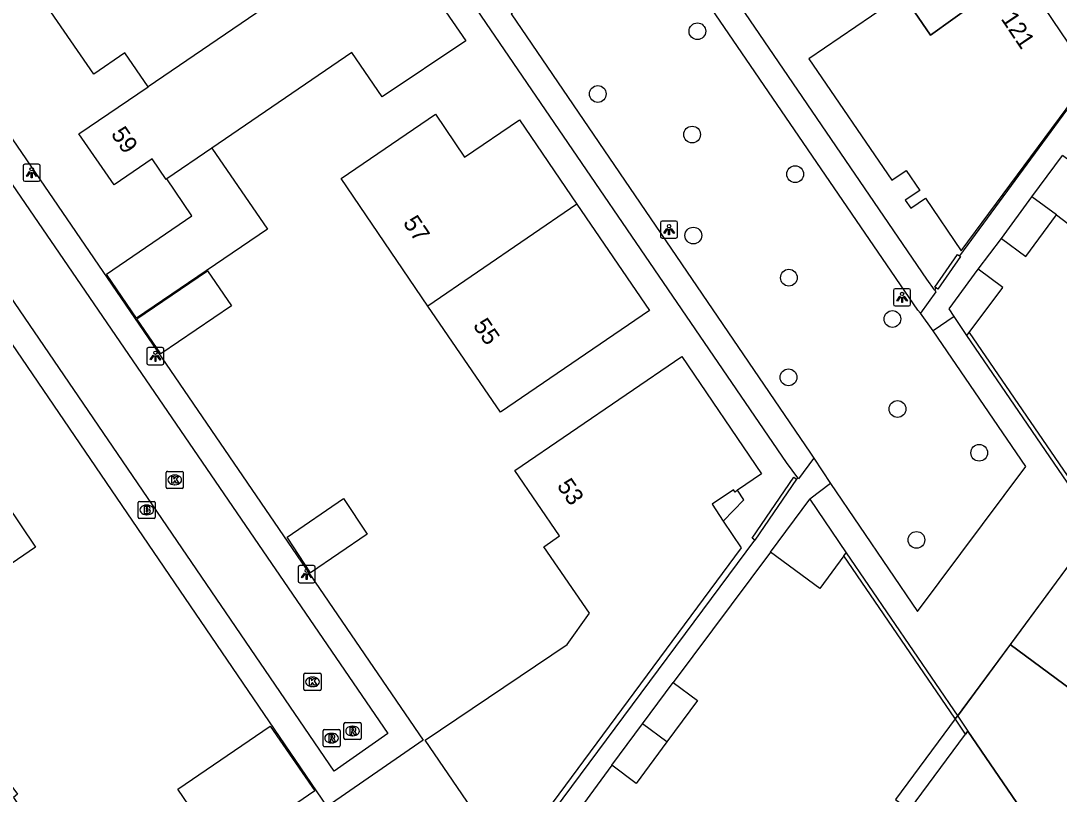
# Model space of a CAD drawing. Extents: x 155275 to 156263, y 382654 to 383635.
# Drawn here: x 155711 to 155771.6, y 383268.4 to 383313.6 of the extents above; entities that cross this region are included whole.
import ezdxf

# ---------------------------------------------------------------- set-up
doc = ezdxf.new("R2010")
doc.units = 0
for name, color, linetype in [('IMGEO_Boom', 7, 'Continuous'), ('IMGEO_Brandkraan', 7, 'Continuous'), ('IMGEO_Kolk', 7, 'Continuous'), ('IMGEO_Lichtpunt', 7, 'Continuous'), ('IMGEO_Muur', 7, 'Continuous'), ('IMGEO_Pand', 7, 'Continuous'), ('IMGEO_Pand_nummerreeks', 7, 'Continuous'), ('IMGEO_Pand_overbouw', 7, 'Continuous'), ('IMGEO_Rijbaan_lokaal_open', 7, 'Continuous'), ('IMGEO_Rioolput', 7, 'Continuous'), ('IMGEO_Voetpad_open', 7, 'Continuous')]:
    doc.layers.add(name, color=color, linetype=linetype)

msp = doc.modelspace()

# ---------------------------------------------------------------- linework, layer by layer
at = {"layer": 'IMGEO_Boom'}
for centre in [(155750.478, 383312.989), (155744.662, 383309.328), (155750.169, 383306.957), (155756.185, 383304.644), (155750.242, 383301.061), (155755.82, 383298.6), (155761.863, 383296.189), (155755.8, 383292.782), (155762.162, 383290.934), (155766.932, 383288.378), (155763.268, 383283.288)]:
    msp.add_circle(centre, 0.489, dxfattribs=at)
at = {"layer": 'IMGEO_Brandkraan'}
for p, q in [((155717.827, 383284.614), (155717.827, 383285.466)), ((155717.902, 383285.54), (155718.754, 383285.54)), ((155718.828, 383285.466), (155718.828, 383284.614)), ((155718.338, 383284.76), (155718.313, 383284.76)), ((155718.315, 383285.32), (155718.34, 383285.32)), ((155718.754, 383284.54), (155717.902, 383284.54))]:
    msp.add_line(p, q, dxfattribs=at)
for points in [[(155717.827, 383284.614), (155717.827, 383285.466)], [(155717.902, 383285.54), (155718.754, 383285.54)], [(155718.828, 383285.466), (155718.828, 383284.614)], [(155718.175, 383285.24), (155718.175, 383284.84), (155718.388, 383284.84)], [(155718.406, 383285.24), (155718.175, 383285.24)], [(155718.354, 383285.159), (155718.3, 383285.159), (155718.3, 383285.083)], [(155718.3, 383285.083), (155718.353, 383285.083)], [(155718.362, 383285.007), (155718.3, 383285.007), (155718.3, 383284.926)], [(155718.3, 383284.926), (155718.362, 383284.926)], [(155718.754, 383284.54), (155717.902, 383284.54)]]:
    msp.add_lwpolyline(points, dxfattribs=at)
for centre, radius, start, end in [((155717.904, 383285.464), 0.0765, 91.55205, 178.44795), ((155717.904, 383285.464), 0.0765, 91.55205, 178.44795), ((155718.752, 383285.464), 0.0765, 1.55205, 88.44795), ((155718.752, 383285.464), 0.0765, 1.55205, 88.44795), ((155718.355, 383285.121), 0.0379, 267.82845, 90.93552), ((155718.363, 383284.966), 0.0404, 269.87594, 90.50774), ((155718.394, 383285.091), 0.251, 268.66757, 293.53466), ((155718.41, 383285.095), 0.145, 59.4692, 91.53667), ((155718.435, 383285.142), 0.0922, 285.51372, 58.15012), ((155718.44, 383284.95), 0.105, 301.31148, 78.98903), ((155717.904, 383284.616), 0.0765, 181.55205, 268.44795), ((155717.904, 383284.616), 0.0765, 181.55205, 268.44795), ((155718.752, 383284.616), 0.0765, 271.55205, 358.44795), ((155718.752, 383284.616), 0.0765, 271.55205, 358.44795)]:
    msp.add_arc(centre, radius, start, end, dxfattribs=at)
for centre, major_axis, ratio, start_param, end_param in [((155718.314, 383285.04), (-0.387, 0.002), 0.722429, 4.712389, 7.853982), ((155718.339, 383285.04), (-0.39, 0.002), 0.717154, 1.570796, 4.712389)]:
    msp.add_ellipse(centre, major_axis=major_axis, ratio=ratio, start_param=start_param, end_param=end_param, dxfattribs=at)
at = {"layer": 'IMGEO_Kolk'}
for p, q in [((155719.465, 383286.367), (155719.465, 383287.219)), ((155719.54, 383287.293), (155720.392, 383287.293)), ((155720.466, 383287.219), (155720.466, 383286.367)), ((155719.953, 383287.073), (155719.978, 383287.073)), ((155720.392, 383286.293), (155719.54, 383286.293)), ((155719.976, 383286.513), (155719.951, 383286.513)), ((155727.507, 383274.576), (155727.507, 383275.428)), ((155727.582, 383275.502), (155728.434, 383275.502)), ((155727.995, 383275.282), (155728.02, 383275.282)), ((155728.508, 383275.428), (155728.508, 383274.576)), ((155728.434, 383274.502), (155727.582, 383274.502)), ((155728.018, 383274.722), (155727.993, 383274.722))]:
    msp.add_line(p, q, dxfattribs=at)
for points in [[(155719.465, 383286.367), (155719.465, 383287.219)], [(155719.54, 383287.293), (155720.392, 383287.293)], [(155720.466, 383287.219), (155720.466, 383286.367)], [(155719.786, 383286.993), (155719.909, 383286.993), (155719.909, 383286.842), (155720.039, 383286.993), (155720.203, 383286.993), (155720.057, 383286.842), (155720.21, 383286.593), (155720.058, 383286.593), (155719.973, 383286.757), (155719.909, 383286.69), (155719.909, 383286.593), (155719.786, 383286.593), (155719.786, 383286.993)], [(155720.392, 383286.293), (155719.54, 383286.293)], [(155727.507, 383274.576), (155727.507, 383275.428)], [(155727.582, 383275.502), (155728.434, 383275.502)], [(155727.828, 383275.202), (155727.951, 383275.202), (155727.951, 383275.051), (155728.081, 383275.202), (155728.245, 383275.202), (155728.099, 383275.051), (155728.252, 383274.802), (155728.1, 383274.802), (155728.015, 383274.966), (155727.951, 383274.899), (155727.951, 383274.802), (155727.828, 383274.802), (155727.828, 383275.202)], [(155728.508, 383275.428), (155728.508, 383274.576)], [(155728.434, 383274.502), (155727.582, 383274.502)]]:
    msp.add_lwpolyline(points, dxfattribs=at)
for centre, start, end in [((155719.542, 383287.217), 91.55205, 178.44795), ((155719.542, 383287.217), 91.55205, 178.44795), ((155720.39, 383287.217), 1.55205, 88.44795), ((155720.39, 383287.217), 1.55205, 88.44795), ((155719.542, 383286.369), 181.55205, 268.44795), ((155719.542, 383286.369), 181.55205, 268.44795), ((155720.39, 383286.369), 271.55205, 358.44795), ((155720.39, 383286.369), 271.55205, 358.44795), ((155727.584, 383275.426), 91.55205, 178.44795), ((155727.584, 383275.426), 91.55205, 178.44795), ((155728.432, 383275.426), 1.55205, 88.44795), ((155728.432, 383275.426), 1.55205, 88.44795), ((155727.584, 383274.578), 181.55205, 268.44795), ((155727.584, 383274.578), 181.55205, 268.44795), ((155728.432, 383274.578), 271.55205, 358.44795), ((155728.432, 383274.578), 271.55205, 358.44795)]:
    msp.add_arc(centre, 0.0765, start, end, dxfattribs=at)
for centre, major_axis, ratio, start_param, end_param in [((155719.952, 383286.793), (-0.387, 0.002), 0.722429, 4.712389, 7.853982), ((155719.977, 383286.793), (-0.39, 0.002), 0.717154, 1.570796, 4.712389), ((155727.994, 383275.002), (-0.387, 0.002), 0.722429, 4.712389, 7.853982), ((155728.019, 383275.002), (-0.39, 0.002), 0.717154, 1.570796, 4.712389)]:
    msp.add_ellipse(centre, major_axis=major_axis, ratio=ratio, start_param=start_param, end_param=end_param, dxfattribs=at)
at = {"layer": 'IMGEO_Lichtpunt'}
for p, q in [((155711.114, 383305.133), (155711.114, 383304.326)), ((155711.114, 383305.133), (155711.114, 383304.326)), ((155712.016, 383305.228), (155711.208, 383305.228)), ((155712.016, 383305.228), (155711.208, 383305.228)), ((155712.11, 383304.326), (155712.11, 383305.133)), ((155712.11, 383304.326), (155712.11, 383305.133)), ((155711.208, 383304.232), (155712.016, 383304.232)), ((155711.208, 383304.232), (155712.016, 383304.232)), ((155748.325, 383301.812), (155748.325, 383301.005)), ((155748.325, 383301.812), (155748.325, 383301.005)), ((155749.227, 383301.907), (155748.419, 383301.907)), ((155749.227, 383301.907), (155748.419, 383301.907)), ((155749.321, 383301.005), (155749.321, 383301.812)), ((155749.321, 383301.005), (155749.321, 383301.812)), ((155748.419, 383300.911), (155749.227, 383300.911)), ((155748.419, 383300.911), (155749.227, 383300.911)), ((155761.93, 383297.854), (155761.93, 383297.047)), ((155761.93, 383297.854), (155761.93, 383297.047)), ((155762.832, 383297.949), (155762.024, 383297.949)), ((155762.832, 383297.949), (155762.024, 383297.949)), ((155762.926, 383297.047), (155762.926, 383297.854)), ((155762.926, 383297.047), (155762.926, 383297.854)), ((155762.024, 383296.953), (155762.832, 383296.953)), ((155762.024, 383296.953), (155762.832, 383296.953)), ((155719.238, 383294.516), (155718.43, 383294.516)), ((155719.238, 383294.516), (155718.43, 383294.516)), ((155718.336, 383294.421), (155718.336, 383293.614)), ((155718.336, 383294.421), (155718.336, 383293.614)), ((155719.332, 383293.614), (155719.332, 383294.421)), ((155719.332, 383293.614), (155719.332, 383294.421)), ((155718.43, 383293.52), (155719.238, 383293.52)), ((155718.43, 383293.52), (155719.238, 383293.52)), ((155728.072, 383281.788), (155727.264, 383281.788)), ((155728.072, 383281.788), (155727.264, 383281.788)), ((155727.17, 383281.693), (155727.17, 383280.886)), ((155727.17, 383281.693), (155727.17, 383280.886)), ((155728.166, 383280.886), (155728.166, 383281.693)), ((155728.166, 383280.886), (155728.166, 383281.693)), ((155727.264, 383280.792), (155728.072, 383280.792)), ((155727.264, 383280.792), (155728.072, 383280.792))]:
    msp.add_line(p, q, dxfattribs=at)
for points in [[(155711.488, 383304.797), (155711.527, 383304.769), (155711.339, 383304.507), (155711.301, 383304.534), (155711.488, 383304.797)], [(155711.7, 383304.769), (155711.738, 383304.796), (155711.925, 383304.534), (155711.886, 383304.506), (155711.7, 383304.769)], [(155711.59, 383304.749), (155711.637, 383304.749), (155711.637, 383304.427), (155711.59, 383304.427), (155711.59, 383304.749)], [(155748.699, 383301.476), (155748.738, 383301.448), (155748.55, 383301.186), (155748.512, 383301.213), (155748.699, 383301.476)], [(155748.801, 383301.428), (155748.848, 383301.428), (155748.848, 383301.106), (155748.801, 383301.106), (155748.801, 383301.428)], [(155748.911, 383301.448), (155748.949, 383301.475), (155749.136, 383301.213), (155749.097, 383301.185), (155748.911, 383301.448)], [(155762.304, 383297.518), (155762.343, 383297.49), (155762.155, 383297.228), (155762.117, 383297.255), (155762.304, 383297.518)], [(155762.516, 383297.49), (155762.554, 383297.517), (155762.741, 383297.255), (155762.702, 383297.227), (155762.516, 383297.49)], [(155762.406, 383297.47), (155762.453, 383297.47), (155762.453, 383297.148), (155762.406, 383297.148), (155762.406, 383297.47)], [(155718.71, 383294.085), (155718.749, 383294.057), (155718.561, 383293.795), (155718.523, 383293.822), (155718.71, 383294.085)], [(155718.812, 383294.037), (155718.859, 383294.037), (155718.859, 383293.715), (155718.812, 383293.715), (155718.812, 383294.037)], [(155718.922, 383294.057), (155718.96, 383294.084), (155719.147, 383293.822), (155719.108, 383293.794), (155718.922, 383294.057)], [(155727.544, 383281.357), (155727.583, 383281.329), (155727.395, 383281.067), (155727.357, 383281.094), (155727.544, 383281.357)], [(155727.646, 383281.309), (155727.693, 383281.309), (155727.693, 383280.987), (155727.646, 383280.987), (155727.646, 383281.309)], [(155727.756, 383281.329), (155727.794, 383281.356), (155727.981, 383281.094), (155727.942, 383281.066), (155727.756, 383281.329)]]:
    msp.add_lwpolyline(points, dxfattribs=at)
for centre in [(155711.613, 383304.931), (155748.824, 383301.61), (155762.429, 383297.652), (155718.835, 383294.219), (155727.669, 383281.491)]:
    msp.add_circle(centre, 0.0994, dxfattribs=at)
for centre, start, end in [((155711.208, 383305.133), 90, 180), ((155711.208, 383305.133), 90, 180), ((155712.016, 383305.133), 0, 90), ((155712.016, 383305.133), 0, 90), ((155711.208, 383304.326), 180, 270), ((155711.208, 383304.326), 180, 270), ((155712.016, 383304.326), 270, 0), ((155712.016, 383304.326), 270, 360), ((155748.419, 383301.812), 90, 180), ((155748.419, 383301.812), 90, 180), ((155749.227, 383301.812), 0, 90), ((155749.227, 383301.812), 0, 90), ((155748.419, 383301.005), 180, 270), ((155748.419, 383301.005), 180, 270), ((155749.227, 383301.005), 270, 0), ((155749.227, 383301.005), 270, 360), ((155762.024, 383297.854), 90, 180), ((155762.024, 383297.854), 90, 180), ((155762.832, 383297.854), 0, 90), ((155762.832, 383297.854), 0, 90), ((155762.024, 383297.047), 180, 270), ((155762.024, 383297.047), 180, 270), ((155762.832, 383297.047), 270, 0), ((155762.832, 383297.047), 270, 360), ((155718.43, 383294.421), 90, 180), ((155718.43, 383294.421), 90, 180), ((155719.238, 383294.421), 0, 90), ((155719.238, 383294.421), 0, 90), ((155718.43, 383293.614), 180, 270), ((155718.43, 383293.614), 180, 270), ((155719.238, 383293.614), 270, 0), ((155719.238, 383293.614), 270, 360), ((155727.264, 383281.693), 90, 180), ((155727.264, 383281.693), 90, 180), ((155728.072, 383281.693), 0, 90), ((155728.072, 383281.693), 0, 90), ((155727.264, 383280.886), 180, 270), ((155727.264, 383280.886), 180, 270), ((155728.072, 383280.886), 270, 0), ((155728.072, 383280.886), 270, 360)]:
    msp.add_arc(centre, 0.0946, start, end, dxfattribs=at)
at = {"layer": 'IMGEO_Muur'}
for points in [[(155764.413, 383298.003), (155764.346, 383298.049), (155765.665, 383299.955), (155765.785, 383299.873)], [(155765.785, 383299.873), (155765.83, 383299.841), (155764.511, 383297.935), (155764.413, 383298.003)], [(155773.847, 383284.078), (155766.213, 383295.227)], [(155766.346, 383295.405), (155773.979, 383284.258)], [(155753.838, 383283.279), (155753.674, 383283.392), (155756.107, 383286.947), (155756.272, 383286.834)], [(155756.272, 383286.834), (155753.838, 383283.279)], [(155765.503, 383272.877), (155759.037, 383282.352)], [(155759.17, 383282.529), (155765.677, 383272.995)], [(155765.503, 383272.877), (155765.677, 383272.995)], [(155766.131, 383271.951), (155765.503, 383272.877)], [(155765.677, 383272.995), (155766.263, 383272.13)]]:
    msp.add_lwpolyline(points, dxfattribs=at)
at = {"layer": 'IMGEO_Pand'}
for points in [[(155718.414, 383309.742), (155717.048, 383311.729), (155715.234, 383310.476), (155711.378, 383316.095), (155714.029, 383317.915), (155716.516, 383314.29), (155724.373, 383319.645), (155722.728, 383322.057), (155727.941, 383325.612), (155731.339, 383320.63), (155730.513, 383320.077), (155731.476, 383318.658)], [(155731.476, 383318.658), (155732.298, 383319.22), (155736.952, 383312.438), (155732.083, 383309.164), (155730.299, 383311.75), (155722.139, 383306.171)], [(155731.476, 383318.658), (155718.414, 383309.742)], [(155773.237, 383310.096), (155772.35, 383311.386), (155772.624, 383311.569), (155769.306, 383316.514), (155764.095, 383312.762), (155762.477, 383315.13), (155756.977, 383311.371), (155761.822, 383304.288), (155762.664, 383304.864), (155763.459, 383303.7), (155762.617, 383303.124), (155762.936, 383302.658), (155763.787, 383303.237), (155765.884, 383300.163), (155773.237, 383310.096)], [(155719.497, 383304.365), (155719.456, 383304.337), (155718.644, 383305.537), (155716.426, 383304.029), (155714.371, 383307.002), (155718.414, 383309.742)], [(155734.744, 383296.945), (155729.681, 383304.386), (155735.196, 383308.156), (155736.885, 383305.645), (155740.09, 383307.82), (155743.449, 383302.891)], [(155722.139, 383306.171), (155725.378, 383301.433), (155717.735, 383296.233), (155715.98, 383298.813), (155720.966, 383302.205), (155719.497, 383304.365)], [(155722.139, 383306.171), (155719.497, 383304.365)], [(155770.012, 383303.314), (155771.797, 383305.735)], [(155771.437, 383302.262), (155772.446, 383301.517), (155774.232, 383303.941), (155773.223, 383304.684), (155771.797, 383305.735)], [(155768.226, 383300.892), (155770.012, 383303.314)], [(155771.437, 383302.262), (155770.012, 383303.314)], [(155743.449, 383302.891), (155747.678, 383296.685), (155738.98, 383290.741), (155734.744, 383296.945)], [(155743.449, 383302.891), (155734.744, 383296.945)], [(155768.226, 383300.892), (155769.652, 383299.841), (155771.437, 383302.262)], [(155717.758, 383296.2), (155721.882, 383299.006), (155723.279, 383296.952), (155719.162, 383294.151), (155717.758, 383296.2)], [(155765.476, 383296.326), (155765.175, 383296.775), (155766.877, 383299.089)], [(155766.346, 383295.405), (155768.311, 383298.034), (155766.877, 383299.089)], [(155766.213, 383295.227), (155765.476, 383296.326)], [(155766.213, 383295.227), (155766.346, 383295.405)], [(155734.583, 383271.594), (155742.867, 383277.178), (155744.174, 383279.002), (155741.521, 383282.885), (155742.428, 383283.521), (155739.813, 383287.344), (155749.57, 383293.989), (155754.229, 383287.144), (155752.824, 383286.188), (155752.675, 383286.086), (155752.585, 383286.218), (155751.334, 383285.368), (155751.99, 383284.392), (155753.037, 383282.834), (155739.444, 383264.478), (155734.583, 383271.594)], [(155705.946, 383278.833), (155705.646, 383279.27), (155704.728, 383278.7), (155707.15, 383275.123), (155698.001, 383268.874), (155697.9, 383269.023), (155697.545, 383268.786), (155697.647, 383268.638), (155697.523, 383268.551), (155694.995, 383272.212), (155694.838, 383272.105), (155693.069, 383274.695), (155696.868, 383277.29), (155696.987, 383277.376), (155697.21, 383277.058), (155699.16, 383278.418), (155698.76, 383278.992), (155698.596, 383278.878), (155698.345, 383279.237), (155709.258, 383286.667), (155711.833, 383282.866), (155705.946, 383278.833)], [(155726.527, 383283.449), (155729.81, 383285.709), (155731.194, 383283.622), (155727.891, 383281.36), (155726.527, 383283.449)], [(155754.741, 383282.576), (155757.038, 383285.669)], [(155757.038, 383285.669), (155759.17, 383282.529)], [(155759.037, 383282.352), (155757.618, 383280.458), (155754.741, 383282.576)], [(155759.037, 383282.352), (155759.17, 383282.529)], [(155747.276, 383272.548), (155749.067, 383274.967)], [(155749.067, 383274.967), (155750.492, 383273.913), (155748.701, 383271.493)], [(155728.147, 383268.629), (155707.057, 383254.188), (155704.717, 383257.623), (155705.227, 383257.972), (155704.294, 383259.337), (155704.145, 383259.236), (155701.658, 383262.871), (155710.458, 383268.888), (155710.791, 383268.434), (155710.55, 383268.256), (155713.354, 383264.091), (155713.617, 383264.267), (155717.71, 383267.089), (155718.705, 383265.728), (155721.105, 383267.326), (155720.14, 383268.738), (155725.534, 383272.422), (155728.147, 383268.629)], [(155745.485, 383270.128), (155747.276, 383272.548)], [(155748.701, 383271.493), (155747.276, 383272.548)], [(155766.263, 383272.13), (155766.131, 383271.951)], [(155769.629, 383267.192), (155766.263, 383272.13)], [(155748.701, 383271.493), (155746.911, 383269.073), (155745.485, 383270.128)], [(155762.867, 383267.527), (155766.131, 383271.951)]]:
    msp.add_lwpolyline(points, dxfattribs=at)
at = {"layer": 'IMGEO_Pand_overbouw'}
for points in [[(155762.477, 383315.13), (155764.095, 383312.762), (155769.306, 383316.514), (155768.426, 383317.815), (155767.787, 383318.759), (155767.416, 383318.505)], [(155751.99, 383284.392), (155753.191, 383285.637), (155752.824, 383286.188), (155752.675, 383286.086), (155752.585, 383286.218), (155751.334, 383285.368)], [(155776.886, 383281.823), (155774.904, 383283.294), (155773.836, 383284.086), (155768.735, 383277.191), (155776.792, 383271.232), (155783.479, 383280.293), (155782.682, 383280.882), (155779.225, 383276.207), (155776.079, 383280.798)], [(155771.65, 383264.258), (155776.792, 383271.232), (155768.735, 383277.191), (155762.039, 383268.14), (155762.867, 383267.527), (155766.131, 383271.951), (155766.263, 383272.13), (155769.629, 383267.192), (155768.939, 383266.259)]]:
    msp.add_lwpolyline(points, close=True, dxfattribs=at)
at = {"layer": 'IMGEO_Rijbaan_lokaal_open'}
msp.add_lwpolyline([(155693.039, 383329.522), (155732.407, 383271.977), (155729.272, 383269.785), (155689.962, 383327.416)], dxfattribs=at)
at = {"layer": 'IMGEO_Rioolput'}
for p, q in [((155728.621, 383271.289), (155728.621, 383272.141)), ((155728.696, 383272.215), (155729.548, 383272.215)), ((155729.622, 383272.141), (155729.622, 383271.289)), ((155729.844, 383271.707), (155729.844, 383272.559)), ((155729.919, 383272.633), (155730.771, 383272.633)), ((155730.332, 383272.413), (155730.357, 383272.413)), ((155730.845, 383272.559), (155730.845, 383271.707)), ((155729.132, 383271.435), (155729.107, 383271.435)), ((155729.109, 383271.995), (155729.134, 383271.995)), ((155730.771, 383271.633), (155729.919, 383271.633)), ((155730.355, 383271.853), (155730.33, 383271.853)), ((155729.548, 383271.215), (155728.696, 383271.215))]:
    msp.add_line(p, q, dxfattribs=at)
for points in [[(155728.621, 383271.289), (155728.621, 383272.141)], [(155728.696, 383272.215), (155729.548, 383272.215)], [(155729.622, 383272.141), (155729.622, 383271.289)], [(155729.844, 383271.707), (155729.844, 383272.559)], [(155729.919, 383272.633), (155730.771, 383272.633)], [(155730.433, 383272.331), (155730.181, 383272.333), (155730.181, 383271.933)], [(155730.181, 383271.933), (155730.305, 383271.933), (155730.305, 383272.095), (155730.316, 383272.095)], [(155730.359, 383272.252), (155730.305, 383272.252), (155730.305, 383272.171)], [(155730.305, 383272.171), (155730.357, 383272.171)], [(155730.363, 383272.066), (155730.434, 383271.933), (155730.574, 383271.933), (155730.509, 383272.059)], [(155730.845, 383272.559), (155730.845, 383271.707)], [(155729.21, 383271.913), (155728.958, 383271.915), (155728.958, 383271.515)], [(155728.958, 383271.515), (155729.082, 383271.515), (155729.082, 383271.677), (155729.093, 383271.677)], [(155729.136, 383271.834), (155729.082, 383271.834), (155729.082, 383271.753)], [(155729.082, 383271.753), (155729.134, 383271.753)], [(155729.14, 383271.648), (155729.211, 383271.515), (155729.351, 383271.515), (155729.286, 383271.641)], [(155730.771, 383271.633), (155729.919, 383271.633)], [(155729.548, 383271.215), (155728.696, 383271.215)]]:
    msp.add_lwpolyline(points, dxfattribs=at)
for centre, radius, start, end in [((155728.698, 383272.139), 0.0765, 91.55205, 178.44795), ((155728.698, 383272.139), 0.0765, 91.55205, 178.44795), ((155729.546, 383272.139), 0.0765, 1.55205, 88.44795), ((155729.546, 383272.139), 0.0765, 1.55205, 88.44795), ((155729.921, 383272.557), 0.0765, 91.55205, 178.44795), ((155729.921, 383272.557), 0.0765, 91.55205, 178.44795), ((155730.315, 383272.042), 0.0533, 26.02933, 88.69889), ((155730.341, 383272.36), 0.19, 274.7715, 282.96867), ((155730.365, 383272.156), 0.0964, 77.00612, 93.18647), ((155730.379, 383272.213), 0.0378, 276.66336, 79.67722), ((155730.432, 383272.221), 0.109, 350.36119, 89.41601), ((155730.43, 383272.221), 0.112, 277.58423, 350.98172), ((155730.414, 383272.006), 0.108, 29.51342, 73.79051), ((155730.769, 383272.557), 0.0765, 1.55205, 88.44795), ((155730.769, 383272.557), 0.0765, 1.55205, 88.44795), ((155729.092, 383271.624), 0.0533, 26.02933, 88.69889), ((155729.118, 383271.942), 0.19, 274.7715, 282.96867), ((155729.142, 383271.738), 0.0964, 77.00612, 93.18647), ((155729.156, 383271.795), 0.0378, 276.66336, 79.67722), ((155729.209, 383271.803), 0.109, 350.36119, 89.41601), ((155729.207, 383271.803), 0.112, 277.58423, 350.98172), ((155729.191, 383271.588), 0.108, 29.51342, 73.79051), ((155729.921, 383271.709), 0.0765, 181.55205, 268.44795), ((155729.921, 383271.709), 0.0765, 181.55205, 268.44795), ((155730.769, 383271.709), 0.0765, 271.55205, 358.44795), ((155730.769, 383271.709), 0.0765, 271.55205, 358.44795), ((155728.698, 383271.291), 0.0765, 181.55205, 268.44795), ((155728.698, 383271.291), 0.0765, 181.55205, 268.44795), ((155729.546, 383271.291), 0.0765, 271.55205, 358.44795), ((155729.546, 383271.291), 0.0765, 271.55205, 358.44795)]:
    msp.add_arc(centre, radius, start, end, dxfattribs=at)
for centre, major_axis, ratio, start_param, end_param in [((155730.331, 383272.133), (-0.387, 0.002), 0.722429, 4.712389, 7.853982), ((155730.356, 383272.133), (-0.39, 0.002), 0.717154, 1.570796, 4.712389), ((155729.108, 383271.715), (-0.387, 0.002), 0.722429, 4.712389, 7.853982), ((155729.133, 383271.715), (-0.39, 0.002), 0.717154, 1.570796, 4.712389)]:
    msp.add_ellipse(centre, major_axis=major_axis, ratio=ratio, start_param=start_param, end_param=end_param, dxfattribs=at)
at = {"layer": 'IMGEO_Voetpad_open'}
for points in [[(155764.327, 383297.885), (155763.878, 383298.522), (155725.382, 383354.939)], [(155804.41, 383349.86), (155805.536, 383351.381), (155804.469, 383352.147), (155772.167, 383308.3), (155772.022, 383308.374), (155765.785, 383299.873)], [(155756.341, 383286.918), (155755.683, 383287.816), (155714.768, 383347.689)], [(155693.884, 383330.96), (155734.469, 383271.59), (155728.87, 383267.725), (155692.93, 383320.467), (155688.369, 383327.082)], [(155763.51, 383296.526), (155763.357, 383296.696), (155747.691, 383319.636), (155739.6, 383314.001), (155757.081, 383288.349), (155757.279, 383288.068)], [(155766.877, 383299.089), (155768.226, 383300.892)], [(155764.327, 383297.885), (155764.4, 383297.778), (155763.51, 383296.526)], [(155764.413, 383298.003), (155764.327, 383297.885)], [(155764.252, 383295.501), (155763.51, 383296.526)], [(155765.476, 383296.326), (155764.252, 383295.501)], [(155758.243, 383286.581), (155763.336, 383279.1), (155769.659, 383287.575), (155764.252, 383295.501)], [(155757.279, 383288.068), (155757.257, 383288.039), (155756.383, 383286.856), (155756.341, 383286.918)], [(155757.279, 383288.068), (155758.243, 383286.581)], [(155756.272, 383286.834), (155756.341, 383286.918)], [(155758.243, 383286.581), (155757.038, 383285.669)], [(155765.677, 383272.995), (155773.847, 383284.078)], [(155722.428, 383238.91), (155721.741, 383237.982), (155720.716, 383238.675), (155753.838, 383283.279)], [(155754.741, 383282.576), (155749.067, 383274.967)], [(155745.485, 383270.128), (155742.752, 383266.412)]]:
    msp.add_lwpolyline(points, dxfattribs=at)

# ---------------------------------------------------------------- texts
at = {"layer": 'IMGEO_Pand_nummerreeks'}
for s, rotation, p in [('121', 303.8616, (155768.169, 383313.722)), ('59', 304.65228, (155716.206, 383306.985)), ('57', 304.07359, (155733.259, 383301.804)), ('55', 304.07359, (155737.346, 383295.807)), ('53', 304.37153, (155742.245, 383286.446))]:
    msp.add_text(s, height=1, rotation=rotation, dxfattribs=at).set_placement(p)

doc.saveas('drawing.dxf')
